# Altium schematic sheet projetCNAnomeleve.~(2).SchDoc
size A4
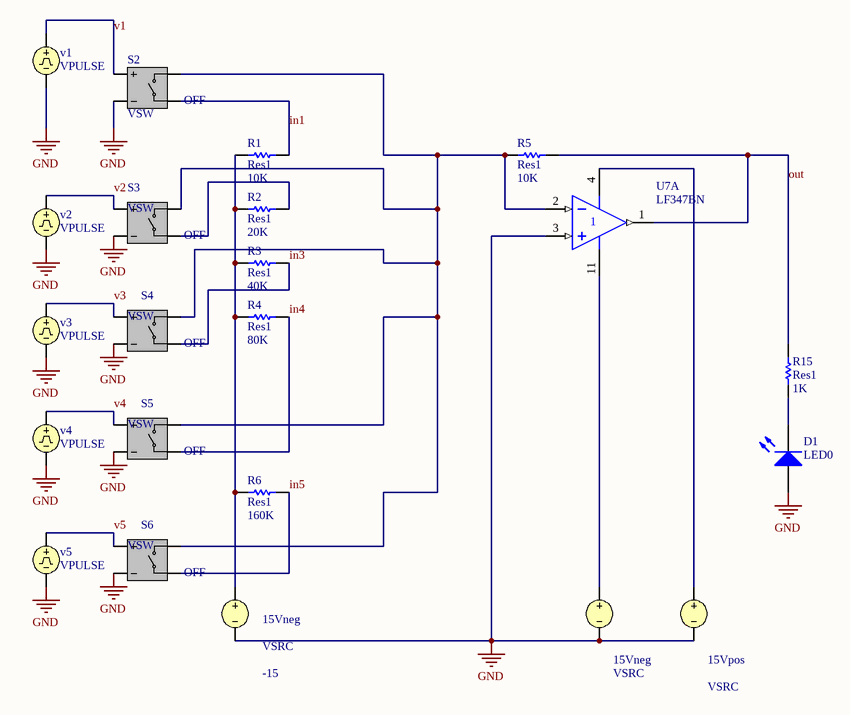
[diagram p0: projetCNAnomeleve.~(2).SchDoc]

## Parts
(Parts that share a designator on the sheet are numbered #1, #2 ... from top to bottom, then left to right.)
15Vneg#1  VSRC  value -15
15Vneg#2  VSRC
15Vpos  VSRC
D1  LED0  [LED-0]
R1  Res1  value 10K  [AXIAL-0.3]
R2  Res1  value 20K  [AXIAL-0.3]
R3  Res1  value 40K  [AXIAL-0.3]
R4  Res1  value 80K  [AXIAL-0.3]
R5  Res1  value 10K  [AXIAL-0.3]
R6  Res1  value 160K  [AXIAL-0.3]
R15  Res1  value 1K  [AXIAL-0.3]
S2  VSW  Initial Condition: OFF
S3  VSW  Initial Condition: OFF
S4  VSW  Initial Condition: OFF
S5  VSW  Initial Condition: OFF
S6  VSW  Initial Condition: OFF
U7  LF347BN  [646-06]  (part A of 4)
v1  VPULSE
v2  VPULSE
v3  VPULSE
v4  VPULSE
v5  VPULSE

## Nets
GND: 15Vneg#1.2 15Vneg#2.2 15Vpos.2 D1.1(A) S2.2(N1-) S3.2(N1-) S4.2(N1-) S5.2(N1-) S6.2(N1-) U7.3(IN+) v1.2 v2.2 v3.2 v4.2 v5.2
in1: R1.2 S2.4(N2-)
in3: R3.2 S4.4(N2-)
in4: R4.2 S5.4(N2-)
in5: R6.2 S6.4(N2-)
out: R5.2 R15.1 U7.1(OUT)
v1: S2.1(N1+) v1.1
v2: S3.1(N1+) v2.1
v3: S4.1(N1+) v3.1
v4: S5.1(N1+) v4.1
v5: S6.1(N1+) v5.1
Net15Vneg#1_1: 15Vneg#1.1 R1.1 R2.1 R3.1 R4.1 R6.1
Net15Vneg#2_1: 15Vneg#2.1 U7.11(V-)
Net15Vpos_1: 15Vpos.1 U7.4(V+)
NetD1_2: D1.2(K) R15.2
NetR2_2: R2.2 S3.4(N2-)
NetR5_1: R5.1 S2.3(N2+) S3.3(N2+) S4.3(N2+) S5.3(N2+) S6.3(N2+) U7.2(IN-)

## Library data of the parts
15Vneg#1 = VSRC: Voltage Source; Note: PCB Footprint - Not required
15Vneg#2 = VSRC: Voltage Source; Note: PCB Footprint - Not required; Value: -15
15Vpos = VSRC: Voltage Source; Note: PCB Footprint - Not required; Value: 15
D1 = LED0: Typical INFRARED GaAs LED
R1-R6 R15 = Res1: Resistor
S2-S6 = VSW: Voltage Controlled Switch
U7 = LF347BN: Quad JFET Input Operational Amplifier, Internally Compensated
v1-v5 = VPULSE: Pulse Voltage Source; Note: PCB Footprint - Not required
